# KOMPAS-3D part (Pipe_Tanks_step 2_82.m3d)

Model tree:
1. X Axis
2. Y Axis
3. Z Axis  (labels: Pipe Dn 50; Bend 90 Dn 50)
     Òîëùèíà ñòåíêè 1 = 1

Referenced files in C:\Documents and Settings\kashirsky\Мои документы\Camtasia Studio\Pipelines3D\Tanks\: Tanks_step 4.a3d
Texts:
  Pipe Dn 50
  Steel ASTM A295
  Three Point Plane
  Plane at Angle
  Line and Point Plane
  Axis through Two Vertices
  Axis of Feature
  Axis of Conical Surface
  Axis through Edge
  Trim by Surface
  Trim by Sketch
  Feature with No History
  Intersection Axis of Two Planes
  Two Line Plane
  Line and Face Plane
  Bend by line
  Hole in sheet body
  Cut in sheet body
  Point in CM
  Linear Dimension from Line to Point
  Surface Finish Symbol
  Geometric Tolerance Symbol
  Leader #1
  Leader #2
  Leader #3
  Shape Deviations and Datum
  Node point number
  Mark of coordination axis
  Node point designation
  Mark/Reference designation with leader
  Mark/reference designation on line
  Mark/Reference designation without leader
  Bend 90 Dn 50
  Plane of section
